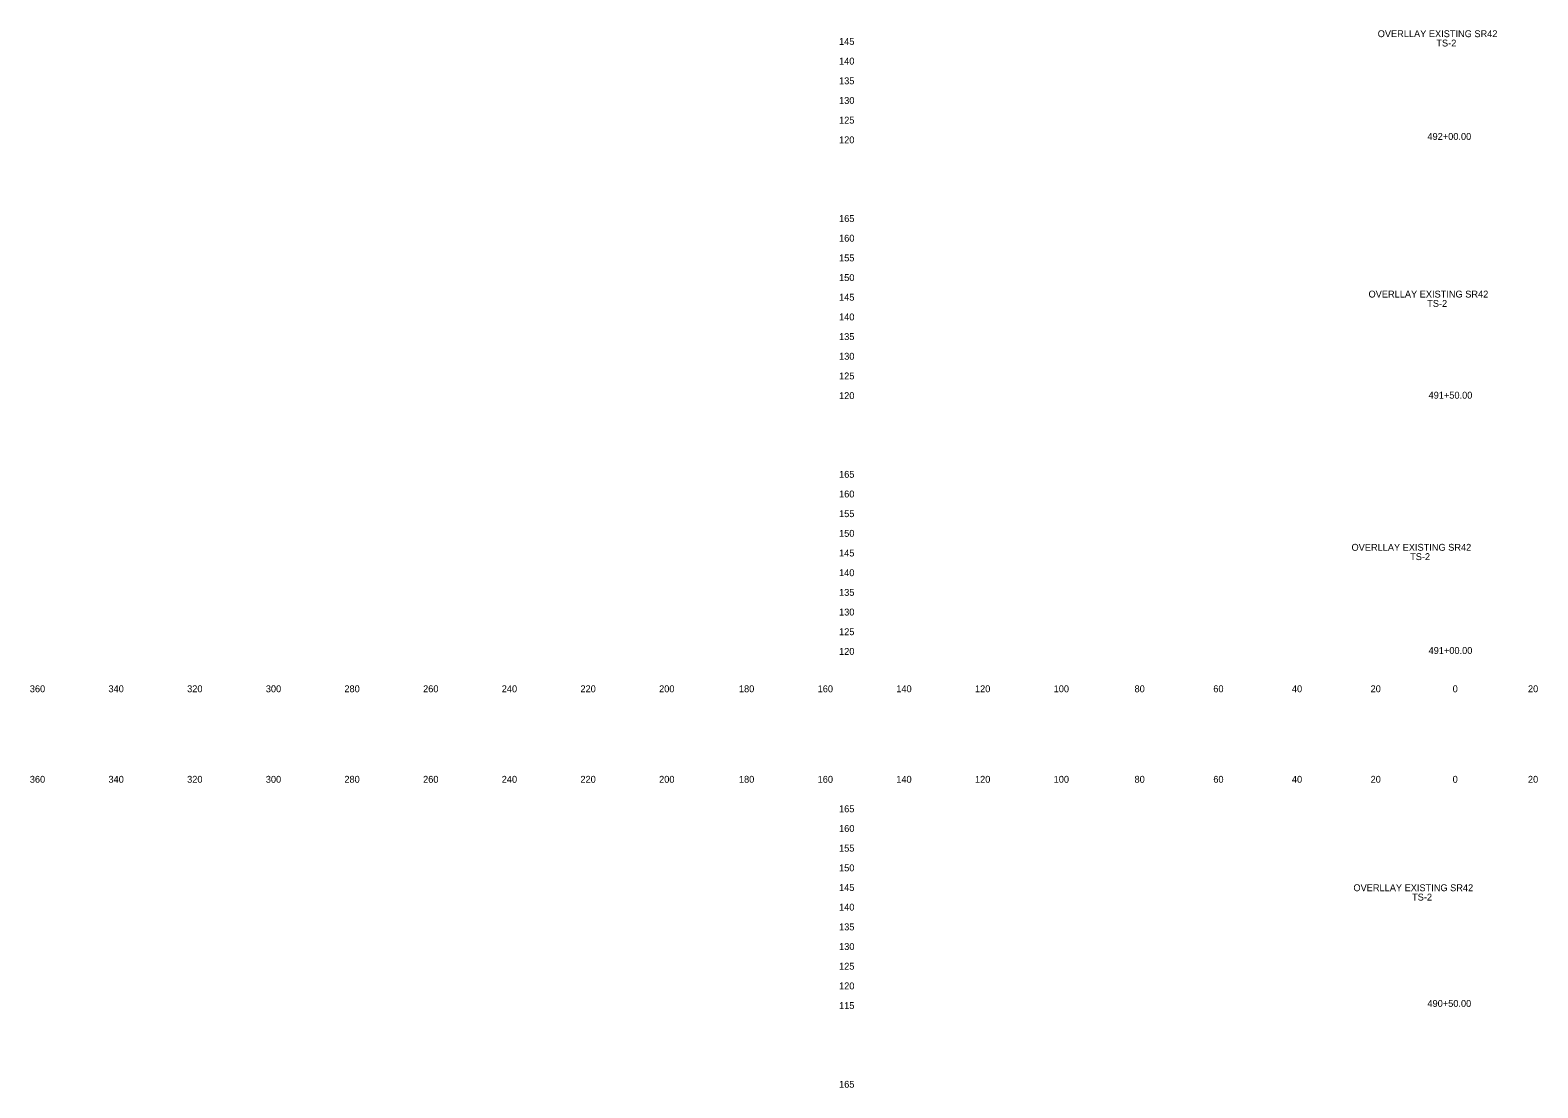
# Model space of a CAD drawing. Extents: x 21281 to 22024, y 6472 to 15198.
# Drawn here: x 21280.5 to 21663.8, y 14654.8 to 14923.6 of the extents above; entities that cross this region are included whole.
import ezdxf

# ---------------------------------------------------------------- set-up
doc = ezdxf.new("R2010")
doc.units = 0
for name, color, linetype in [('Draft_XS_Grid', 7, 'Continuous'), ('Draft_XS_Text', 7, 'Continuous'), ('SLOPE_STAKES_FILL', 7, 'Continuous')]:
    doc.layers.add(name, color=color, linetype=linetype)

msp = doc.modelspace()

# ---------------------------------------------------------------- texts
at = {"layer": 'Draft_XS_Grid'}
for s, p in [('  145  ', (21484.84, 14919.84)), ('  140  ', (21484.84, 14914.84)), ('  135  ', (21484.84, 14909.84)), ('  130  ', (21484.84, 14904.84)), ('  125  ', (21484.84, 14899.84)), ('  120  ', (21484.84, 14894.84)), ('  165  ', (21484.84, 14874.84)), ('  160  ', (21484.84, 14869.84)), ('  155  ', (21484.84, 14864.84)), ('  150  ', (21484.84, 14859.84)), ('  145  ', (21484.84, 14854.84)), ('  140  ', (21484.84, 14849.84)), ('  135  ', (21484.84, 14844.84)), ('  130  ', (21484.84, 14839.84)), ('  125  ', (21484.84, 14834.84)), ('  120  ', (21484.84, 14829.84)), ('  165  ', (21484.84, 14809.84)), ('  160  ', (21484.84, 14804.84)), ('  155  ', (21484.84, 14799.84)), ('  150  ', (21484.84, 14794.84)), ('  145  ', (21484.84, 14789.84)), ('  140  ', (21484.84, 14784.84)), ('  135  ', (21484.84, 14779.84)), ('  130  ', (21484.84, 14774.84)), ('  125  ', (21484.84, 14769.84)), ('  120  ', (21484.84, 14764.84)), ('  165  ', (21484.84, 14724.84)), ('  160  ', (21484.84, 14719.84)), ('  155  ', (21484.84, 14714.84)), ('  150  ', (21484.84, 14709.84)), ('  145  ', (21484.84, 14704.84)), ('  140  ', (21484.84, 14699.84)), ('  135  ', (21484.84, 14694.84)), ('  130  ', (21484.84, 14689.84)), ('  125  ', (21484.84, 14684.84)), ('  120  ', (21484.84, 14679.84)), ('  115  ', (21484.84, 14674.84)), ('  165  ', (21484.84, 14654.84))]:
    msp.add_text(s, height=1.75, dxfattribs=at).set_placement(p)
at = {"layer": 'Draft_XS_Text'}
for s, p in [('  360  ', (21279.14, 14755.34)), ('  340  ', (21299.13, 14755.34)), ('  320  ', (21319.13, 14755.34)), ('  300  ', (21339.13, 14755.34)), ('  280  ', (21359.1, 14755.34)), ('  260  ', (21379.11, 14755.34)), ('  240  ', (21399.1, 14755.34)), ('  220  ', (21419.1, 14755.34)), ('  200  ', (21439.1, 14755.34)), ('  180  ', (21459.39, 14755.34)), ('  160  ', (21479.4, 14755.34)), ('  140  ', (21499.39, 14755.34)), ('  120  ', (21519.39, 14755.34)), ('  100  ', (21539.39, 14755.34)), ('  80  ', (21559.95, 14755.34)), ('  60  ', (21579.97, 14755.34)), ('  40  ', (21599.95, 14755.34)), ('  20  ', (21619.95, 14755.34)), ('  0  ', (21640.81, 14755.34)), ('  0  ', (21640.81, 14755.34)), ('  20  ', (21659.95, 14755.34)), ('  360  ', (21279.14, 14732.34)), ('  340  ', (21299.13, 14732.34)), ('  320  ', (21319.13, 14732.34)), ('  300  ', (21339.13, 14732.34)), ('  280  ', (21359.1, 14732.34)), ('  260  ', (21379.11, 14732.34)), ('  240  ', (21399.1, 14732.34)), ('  220  ', (21419.1, 14732.34)), ('  200  ', (21439.1, 14732.34)), ('  180  ', (21459.39, 14732.34)), ('  160  ', (21479.4, 14732.34)), ('  140  ', (21499.39, 14732.34)), ('  120  ', (21519.39, 14732.34)), ('  100  ', (21539.39, 14732.34)), ('  80  ', (21559.95, 14732.34)), ('  60  ', (21579.97, 14732.34)), ('  40  ', (21599.95, 14732.34)), ('  20  ', (21619.95, 14732.34)), ('  0  ', (21640.81, 14732.34)), ('  0  ', (21640.81, 14732.34)), ('  20  ', (21659.95, 14732.34))]:
    msp.add_text(s, height=1.75, dxfattribs=at).set_placement(p)
at = {"layer": 'SLOPE_STAKES_FILL'}
for s, p in [('OVERLLAY EXISTING SR42', (21623.06, 14921.81)), ('TS-2', (21637.97, 14919.44)), ('  492+00.00  ', (21634.4, 14895.7)), ('OVERLLAY EXISTING SR42', (21620.73, 14855.64)), ('TS-2', (21635.64, 14853.26)), ('  491+50.00  ', (21634.69, 14829.95)), ('OVERLLAY EXISTING SR42', (21616.4, 14791.29)), ('TS-2', (21631.3, 14788.92)), ('  491+00.00  ', (21634.69, 14765.07)), ('OVERLLAY EXISTING SR42', (21616.89, 14704.78)), ('TS-2', (21631.8, 14702.41)), ('  490+50.00  ', (21634.4, 14675.38))]:
    msp.add_text(s, height=1.75, dxfattribs=at).set_placement(p)

doc.saveas('drawing.dxf')
